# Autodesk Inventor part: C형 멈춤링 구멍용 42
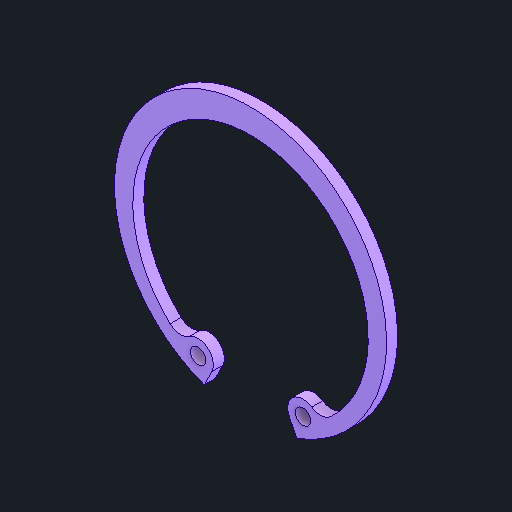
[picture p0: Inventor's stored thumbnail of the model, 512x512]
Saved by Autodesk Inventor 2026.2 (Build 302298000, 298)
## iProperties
Created: 2025-11
Part Number: C형 멈춤링 구멍용 42
Material: 강철, 연강
Description: 리테이닝 링(C형)
Document SubType Name: Modeling
Designer: PC2-07
Density: 7.85 g/cm^3
Appearance: 기본값
Author: jhkim
Sending System: Autodesk Inventor 2026
Preprocessor: ST-DEVELOPER v20.1
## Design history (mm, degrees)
feature "Solid1"
node "솔리드1"
